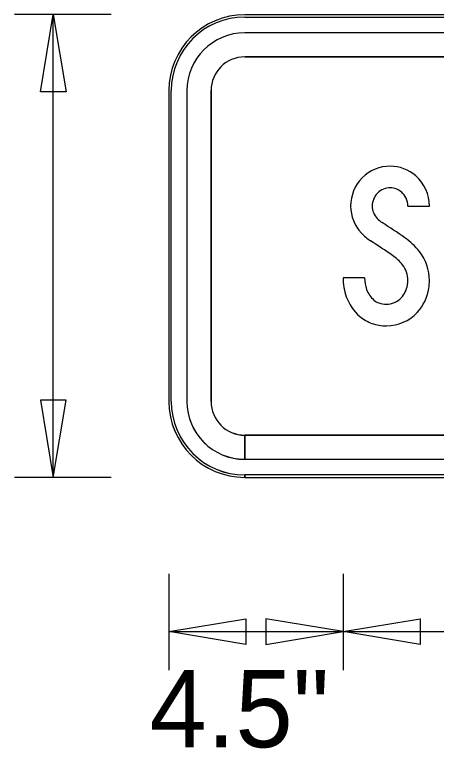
# Model space of a CAD drawing. Extents: x 57.2 to 85.4, y 153.3 to 173.4.
# Drawn here: x 78.575 to 79.486, y 169.257 to 170.843 of the extents above; entities that cross this region are included whole.
import ezdxf

# ---------------------------------------------------------------- set-up
doc = ezdxf.new("R2010")
doc.units = 0
for name, color, linetype in [('GSBWFILL', 7, 'Continuous'), ('GSCOLORFILL', 7, 'Continuous'), ('GSDIMS', 7, 'Continuous'), ('GSOUTLINE', 7, 'Continuous')]:
    doc.layers.add(name, color=color, linetype=linetype)

msp = doc.modelspace()

# ---------------------------------------------------------------- linework, layer by layer
at = {"layer": 'GSBWFILL'}
for p, q in [((81.2439, 170.8428), (79.0721, 170.8428)), ((81.2439, 170.8428), (79.0721, 170.8428)), ((81.2439, 170.8037), (79.0721, 170.8037)), ((81.2439, 170.8037), (79.0721, 170.8037)), ((79.0721, 170.7517), (81.2439, 170.7517)), ((79.0721, 170.7516), (81.2439, 170.7516)), ((78.908, 170.6787), (78.908, 170.0069)), ((78.908, 170.6787), (78.908, 170.0068)), ((78.9471, 170.6787), (78.9471, 170.0069)), ((78.9471, 170.6787), (78.9471, 170.0068)), ((78.9992, 170.0069), (78.9992, 170.6787)), ((78.9992, 170.0068), (78.9992, 170.6787)), ((79.0721, 169.8819), (79.0721, 169.934)), ((79.0721, 169.8818), (79.0721, 169.9339)), ((81.2439, 169.934), (79.0726, 169.934)), ((79.0726, 169.934), (79.0726, 169.8819)), ((81.2439, 169.9339), (79.0726, 169.9339)), ((79.0726, 169.9339), (79.0726, 169.8818)), ((79.0726, 169.8819), (81.2439, 169.8819)), ((79.0726, 169.8818), (81.2439, 169.8818)), ((79.0721, 169.8428), (81.2439, 169.8428)), ((79.0721, 169.8428), (81.2439, 169.8428))]:
    msp.add_line(p, q, dxfattribs=at)
for points in [[(79.4246, 170.4292), (79.4713, 170.4292)], [(79.3313, 170.2742), (79.2846, 170.2742)]]:
    msp.add_lwpolyline(points, dxfattribs=at)
for centre, radius, start, end in [((79.0721, 170.6787), 0.1641, 90, 180), ((79.0721, 170.6787), 0.1641, 90, 180), ((79.0721, 170.6787), 0.125, 90, 180), ((79.0721, 170.6787), 0.125, 90, 180), ((79.0721, 170.6787), 0.0729, 90, 180), ((79.0721, 170.6787), 0.0729, 90, 180), ((79.0721, 170.0069), 0.1641, 180, 270), ((79.0721, 170.0068), 0.1641, 180, 270), ((79.0721, 170.0069), 0.125, 180, 270), ((79.0721, 170.0068), 0.125, 180, 270), ((79.0721, 170.0069), 0.0729, 180, 270), ((79.0721, 170.0068), 0.0729, 180, 270)]:
    msp.add_arc(centre, radius, start, end, dxfattribs=at)
for centre, major_axis, start_param, end_param in [((79.3869, 170.4294), (0, 0.0859), 6.283184, 7.853982), ((79.3869, 170.4323), (0, 0.0829), 5.561989, 6.283185), ((79.3842, 170.4292), (0, 0.0871), 4.712389, 5.561989), ((79.3869, 170.4294), (0, 0.0392), 6.283183, 7.853981), ((79.3869, 170.4323), (0, 0.0363), 5.561989, 6.283185), ((79.3842, 170.4292), (0, 0.0405), 4.712389, 5.561989), ((79.3871, 170.4294), (0, 0.086), 1.570796, 2.321595), ((79.3871, 170.4294), (0, 0.0394), 1.570796, 2.321595), ((79.4013, 170.4427), (0, 0.0588), 2.321595, 2.56746), ((78.3039, 168.746), (0, 1.9619), 5.679143, 5.709053), ((79.4013, 170.4427), (0, 0.1054), 2.321595, 2.56746), ((78.3039, 168.746), (0, 1.9152), 5.679143, 5.709053), ((79.3366, 170.2426), (0, 0.1435), 5.373599, 5.679143), ((79.3366, 170.2426), (0, 0.0969), 5.373599, 5.679143), ((79.3698, 170.2684), (0, 0.1015), 4.712389, 5.373599), ((79.3698, 170.2684), (0, 0.0549), 4.712389, 5.373599), ((79.4076, 170.2742), (0, 0.1229), 1.570808, 1.909921), ((79.4076, 170.2742), (0, 0.0763), 1.570816, 1.909918), ((79.3603, 170.2684), (0, 0.0643), 4.552917, 4.712389), ((79.3603, 170.2684), (0, 0.111), 4.552917, 4.712389), ((79.3722, 170.2665), (0, 0.0523), 3.967076, 4.552917), ((79.3865, 170.2668), (0, 0.0539), 1.909925, 2.431476), ((79.3722, 170.2665), (0, 0.099), 3.967076, 4.552917), ((79.3865, 170.2668), (0, 0.1006), 1.909925, 2.431476), ((79.3729, 170.2509), (0, 0.033), 2.431476, 2.811358), ((79.3786, 170.2605), (0, 0.0435), 3.141593, 3.967076), ((79.3786, 170.2678), (0, 0.0508), 2.811358, 3.141593), ((79.3729, 170.2509), (0, 0.0796), 2.431476, 2.811358), ((79.3786, 170.2605), (0, 0.0902), 3.141593, 3.967076), ((79.3786, 170.2678), (0, 0.0975), 2.811358, 3.141593)]:
    msp.add_ellipse(centre, major_axis=major_axis, ratio=0.999991, start_param=start_param, end_param=end_param, dxfattribs=at)
at = {"layer": 'GSCOLORFILL'}
for p, q in [((81.2439, 170.8428), (79.0721, 170.8428)), ((81.2439, 170.8428), (79.0721, 170.8428)), ((81.2439, 170.8428), (79.0721, 170.8428)), ((81.2439, 170.8428), (79.0721, 170.8428)), ((79.0721, 170.8376), (81.2439, 170.8376)), ((79.0721, 170.8376), (81.2439, 170.8376)), ((81.2439, 170.8037), (79.0721, 170.8037)), ((81.2439, 170.8037), (79.0721, 170.8037)), ((79.0721, 170.7517), (81.2439, 170.7517)), ((79.0721, 170.7516), (81.2439, 170.7516)), ((78.908, 170.6787), (78.908, 170.0069)), ((78.908, 170.6787), (78.908, 170.0069)), ((78.908, 170.6787), (78.908, 170.0068)), ((78.908, 170.6787), (78.908, 170.0068)), ((78.9132, 170.0069), (78.9132, 170.6787)), ((78.9132, 170.0068), (78.9132, 170.6787)), ((78.9471, 170.6787), (78.9471, 170.0069)), ((78.9471, 170.6787), (78.9471, 170.0068)), ((78.9992, 170.0069), (78.9992, 170.6787)), ((78.9992, 170.0068), (78.9992, 170.6787)), ((79.0721, 169.8819), (79.0721, 169.934)), ((79.0721, 169.8818), (79.0721, 169.9339)), ((81.2439, 169.934), (79.0726, 169.934)), ((79.0726, 169.934), (79.0726, 169.8819)), ((81.2439, 169.9339), (79.0726, 169.9339)), ((79.0726, 169.9339), (79.0726, 169.8818)), ((79.0726, 169.8819), (81.2439, 169.8819)), ((79.0726, 169.8818), (81.2439, 169.8818)), ((79.0721, 169.8428), (79.0721, 169.848)), ((81.2439, 169.848), (79.0721, 169.848)), ((79.0721, 169.848), (79.0721, 169.8428)), ((79.0721, 169.8428), (79.0721, 169.848)), ((81.2439, 169.848), (79.0721, 169.848)), ((79.0721, 169.848), (79.0721, 169.8428)), ((79.0721, 169.8428), (81.2439, 169.8428)), ((79.0721, 169.8428), (81.2439, 169.8428)), ((79.0721, 169.8428), (81.2439, 169.8428)), ((79.0721, 169.8428), (81.2439, 169.8428))]:
    msp.add_line(p, q, dxfattribs=at)
for points in [[(79.4246, 170.4292), (79.4713, 170.4292)], [(79.3313, 170.2742), (79.2846, 170.2742)]]:
    msp.add_lwpolyline(points, dxfattribs=at)
for centre, radius, start, end in [((79.0721, 170.6787), 0.1641, 90, 180), ((79.0721, 170.6787), 0.1641, 90, 180), ((79.0721, 170.6787), 0.1641, 90, 180), ((79.0721, 170.6787), 0.1641, 90, 180), ((79.0721, 170.6787), 0.1589, 90, 180), ((79.0721, 170.6787), 0.1589, 90, 180), ((79.0721, 170.6787), 0.125, 90, 180), ((79.0721, 170.6787), 0.125, 90, 180), ((79.0721, 170.6787), 0.0729, 90, 180), ((79.0721, 170.6787), 0.0729, 90, 180), ((79.0721, 170.0069), 0.1641, 180, 270), ((79.0721, 170.0069), 0.1641, 180, 270), ((79.0721, 170.0068), 0.1641, 180, 270), ((79.0721, 170.0068), 0.1641, 180, 270), ((79.0721, 170.0069), 0.1589, 180, 270), ((79.0721, 170.0068), 0.1589, 180, 270), ((79.0721, 170.0069), 0.125, 180, 270), ((79.0721, 170.0068), 0.125, 180, 270), ((79.0721, 170.0069), 0.0729, 180, 270), ((79.0721, 170.0068), 0.0729, 180, 270)]:
    msp.add_arc(centre, radius, start, end, dxfattribs=at)
for centre, major_axis, start_param, end_param in [((79.3869, 170.4294), (0, 0.0859), 6.283184, 7.853982), ((79.3869, 170.4323), (0, 0.0829), 5.561989, 6.283185), ((79.3842, 170.4292), (0, 0.0871), 4.712389, 5.561989), ((79.3869, 170.4294), (0, 0.0392), 6.283183, 7.853981), ((79.3869, 170.4323), (0, 0.0363), 5.561989, 6.283185), ((79.3842, 170.4292), (0, 0.0405), 4.712389, 5.561989), ((79.3871, 170.4294), (0, 0.086), 1.570796, 2.321595), ((79.3871, 170.4294), (0, 0.0394), 1.570796, 2.321595), ((79.4013, 170.4427), (0, 0.0588), 2.321595, 2.56746), ((78.3039, 168.746), (0, 1.9619), 5.679143, 5.709053), ((79.4013, 170.4427), (0, 0.1054), 2.321595, 2.56746), ((78.3039, 168.746), (0, 1.9152), 5.679143, 5.709053), ((79.3366, 170.2426), (0, 0.1435), 5.373599, 5.679143), ((79.3366, 170.2426), (0, 0.0969), 5.373599, 5.679143), ((79.3698, 170.2684), (0, 0.1015), 4.712389, 5.373599), ((79.3698, 170.2684), (0, 0.0549), 4.712389, 5.373599), ((79.4076, 170.2742), (0, 0.1229), 1.570808, 1.909921), ((79.4076, 170.2742), (0, 0.0763), 1.570816, 1.909918), ((79.3603, 170.2684), (0, 0.0643), 4.552917, 4.712389), ((79.3603, 170.2684), (0, 0.111), 4.552917, 4.712389), ((79.3722, 170.2665), (0, 0.0523), 3.967076, 4.552917), ((79.3865, 170.2668), (0, 0.0539), 1.909925, 2.431476), ((79.3722, 170.2665), (0, 0.099), 3.967076, 4.552917), ((79.3865, 170.2668), (0, 0.1006), 1.909925, 2.431476), ((79.3729, 170.2509), (0, 0.033), 2.431476, 2.811358), ((79.3786, 170.2605), (0, 0.0435), 3.141593, 3.967076), ((79.3786, 170.2678), (0, 0.0508), 2.811358, 3.141593), ((79.3729, 170.2509), (0, 0.0796), 2.431476, 2.811358), ((79.3786, 170.2605), (0, 0.0902), 3.141593, 3.967076), ((79.3786, 170.2678), (0, 0.0975), 2.811358, 3.141593)]:
    msp.add_ellipse(centre, major_axis=major_axis, ratio=0.999991, start_param=start_param, end_param=end_param, dxfattribs=at)
at = {"layer": 'GSDIMS'}
for p, q in [((78.783, 170.8429), (78.5746, 170.8429)), ((78.658, 169.8428), (78.658, 170.8429)), ((78.783, 170.8429), (78.783, 170.8429)), ((78.783, 169.8428), (78.5746, 169.8428)), ((78.783, 169.8428), (78.783, 169.8428)), ((78.908, 169.6344), (78.908, 169.4261)), ((78.908, 169.6344), (78.908, 169.4261)), ((79.2846, 169.6344), (79.2846, 169.4261)), ((79.2846, 169.6344), (79.2846, 169.4261)), ((78.908, 169.5094), (79.2846, 169.5094)), ((79.2846, 169.5094), (81.0314, 169.5094))]:
    msp.add_line(p, q, dxfattribs=at)
for points in [[(78.658, 170.8429), (78.6858, 170.6762), (78.6302, 170.6762)], [(78.658, 169.8428), (78.6858, 170.0094), (78.6302, 170.0094)], [(78.908, 169.5094), (79.0746, 169.5372), (79.0746, 169.4817)], [(79.2846, 169.5094), (79.118, 169.5372), (79.118, 169.4817)], [(79.2846, 169.5094), (79.4513, 169.5372), (79.4513, 169.4817)]]:
    msp.add_lwpolyline(points, close=True, dxfattribs=at)
at = {"layer": 'GSOUTLINE'}
for p, q in [((81.2439, 170.8428), (79.0721, 170.8428)), ((81.2439, 170.8428), (79.0721, 170.8428)), ((81.2439, 170.8037), (79.0721, 170.8037)), ((81.2439, 170.8037), (79.0721, 170.8037)), ((81.2439, 170.7517), (79.0721, 170.7517)), ((81.2439, 170.7516), (79.0721, 170.7516)), ((78.908, 170.6787), (78.908, 170.0069)), ((78.908, 170.6787), (78.908, 170.0068)), ((78.9471, 170.6787), (78.9471, 170.0069)), ((78.9471, 170.6787), (78.9471, 170.0068)), ((78.9992, 170.6787), (78.9992, 170.0069)), ((78.9992, 170.6787), (78.9992, 170.0068)), ((79.0721, 169.934), (81.2439, 169.934)), ((79.0721, 169.9339), (81.2439, 169.9339)), ((79.0721, 169.8819), (81.2439, 169.8819)), ((79.0721, 169.8818), (81.2439, 169.8818)), ((79.0721, 169.8428), (81.2439, 169.8428)), ((79.0721, 169.8428), (81.2439, 169.8428))]:
    msp.add_line(p, q, dxfattribs=at)
for points in [[(79.4246, 170.4292), (79.4713, 170.4292)], [(79.3313, 170.2742), (79.2846, 170.2742)]]:
    msp.add_lwpolyline(points, dxfattribs=at)
for centre, radius, start, end in [((79.0721, 170.6787), 0.1641, 90, 180), ((79.0721, 170.6787), 0.1641, 90, 180), ((79.0721, 170.6787), 0.125, 90, 180), ((79.0721, 170.6787), 0.125, 90, 180), ((79.0721, 170.6787), 0.0729, 90, 180), ((79.0721, 170.6787), 0.0729, 90, 180), ((79.0721, 170.0069), 0.1641, 180, 270), ((79.0721, 170.0068), 0.1641, 180, 270), ((79.0721, 170.0069), 0.125, 180, 270), ((79.0721, 170.0068), 0.125, 180, 270), ((79.0721, 170.0069), 0.0729, 180, 270), ((79.0721, 170.0068), 0.0729, 180, 270)]:
    msp.add_arc(centre, radius, start, end, dxfattribs=at)
for centre, major_axis, start_param, end_param in [((79.3869, 170.4294), (0, 0.0859), 6.283184, 7.853982), ((79.3869, 170.4323), (0, 0.0829), 5.561989, 6.283185), ((79.3842, 170.4292), (0, 0.0871), 4.712389, 5.561989), ((79.3869, 170.4294), (0, 0.0392), 6.283183, 7.853981), ((79.3869, 170.4323), (0, 0.0363), 5.561989, 6.283185), ((79.3842, 170.4292), (0, 0.0405), 4.712389, 5.561989), ((79.3871, 170.4294), (0, 0.086), 1.570796, 2.321595), ((79.3871, 170.4294), (0, 0.0394), 1.570796, 2.321595), ((79.4013, 170.4427), (0, 0.0588), 2.321595, 2.56746), ((78.3039, 168.746), (0, 1.9619), 5.679143, 5.709053), ((79.4013, 170.4427), (0, 0.1054), 2.321595, 2.56746), ((78.3039, 168.746), (0, 1.9152), 5.679143, 5.709053), ((79.3366, 170.2426), (0, 0.1435), 5.373599, 5.679143), ((79.3366, 170.2426), (0, 0.0969), 5.373599, 5.679143), ((79.3698, 170.2684), (0, 0.1015), 4.712389, 5.373599), ((79.3698, 170.2684), (0, 0.0549), 4.712389, 5.373599), ((79.4076, 170.2742), (0, 0.1229), 1.570808, 1.909921), ((79.4076, 170.2742), (0, 0.0763), 1.570816, 1.909918), ((79.3603, 170.2684), (0, 0.0643), 4.552917, 4.712389), ((79.3603, 170.2684), (0, 0.111), 4.552917, 4.712389), ((79.3722, 170.2665), (0, 0.0523), 3.967076, 4.552917), ((79.3865, 170.2668), (0, 0.0539), 1.909925, 2.431476), ((79.3722, 170.2665), (0, 0.099), 3.967076, 4.552917), ((79.3865, 170.2668), (0, 0.1006), 1.909925, 2.431476), ((79.3729, 170.2509), (0, 0.033), 2.431476, 2.811358), ((79.3786, 170.2605), (0, 0.0435), 3.141593, 3.967076), ((79.3786, 170.2678), (0, 0.0508), 2.811358, 3.141593), ((79.3729, 170.2509), (0, 0.0796), 2.431476, 2.811358), ((79.3786, 170.2605), (0, 0.0902), 3.141593, 3.967076), ((79.3786, 170.2678), (0, 0.0975), 2.811358, 3.141593)]:
    msp.add_ellipse(centre, major_axis=major_axis, ratio=0.999991, start_param=start_param, end_param=end_param, dxfattribs=at)

# ---------------------------------------------------------------- texts
at = {"layer": 'GSDIMS'}
msp.add_text('4.5"', height=0.16667, dxfattribs=at).set_placement((78.8661, 169.2594))

doc.saveas('drawing.dxf')
